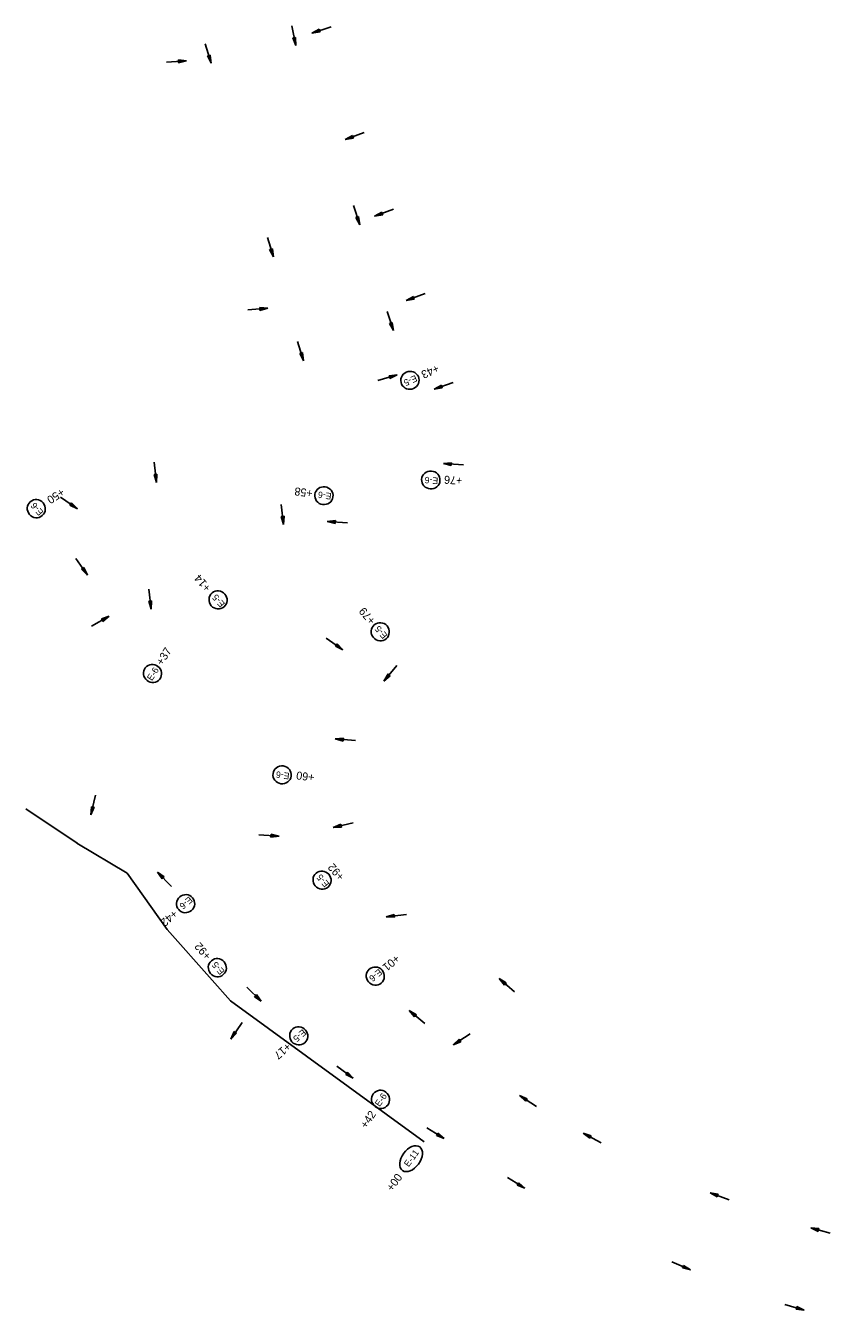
# Model space of a CAD drawing. Extents: x 918344 to 920005, y 1764082 to 1766125.
# Drawn here: x 919402 to 920005, y 1764082 to 1765046 of the extents above; entities that cross this region are included whole.
import ezdxf

# ---------------------------------------------------------------- set-up
doc = ezdxf.new("R2010")
doc.units = 0
for name, color, linetype in [('43', 7, 'Continuous'), ('44', 7, 'Continuous'), ('EC_CG', 7, 'Continuous'), ('Level 1', 7, 'Continuous')]:
    doc.layers.add(name, color=color, linetype=linetype)

msp = doc.modelspace()

# ---------------------------------------------------------------- linework, layer by layer
at = {"layer": '43'}
for p, q in [((919602.32, 1765036.58), (919604.42, 1765036.98)), ((919604.51, 1765030.81), (919602.32, 1765036.58)), ((919604.42, 1765036.98), (919604.51, 1765030.81)), ((919616.63, 1765040.13), (919622.07, 1765043.04)), ((919622.74, 1765041), (919616.63, 1765040.13)), ((919622.07, 1765043.04), (919622.74, 1765041)), ((919516.67, 1765017.94), (919516.5, 1765020.08)), ((919516.5, 1765020.08), (919522.64, 1765019.48)), ((919522.64, 1765019.48), (919516.67, 1765017.94)), ((919538.23, 1765023.02), (919540.28, 1765023.64)), ((919541.01, 1765017.51), (919538.23, 1765023.02)), ((919540.28, 1765023.64), (919541.01, 1765017.51)), ((919641.62, 1764960.43), (919646.97, 1764963.51)), ((919647.7, 1764961.49), (919641.62, 1764960.43)), ((919646.97, 1764963.51), (919647.7, 1764961.49)), ((919649.55, 1764901.92), (919651.6, 1764902.57)), ((919652.42, 1764896.46), (919649.55, 1764901.92)), ((919651.6, 1764902.57), (919652.42, 1764896.46)), ((919663.6, 1764902.91), (919668.95, 1764905.99)), ((919669.68, 1764903.97), (919663.6, 1764902.91)), ((919668.95, 1764905.99), (919669.68, 1764903.97)), ((919584.9, 1764877.8), (919586.96, 1764878.42)), ((919587.69, 1764872.29), (919584.9, 1764877.8)), ((919586.96, 1764878.42), (919587.69, 1764872.29)), ((919687.31, 1764839.63), (919692.66, 1764842.71)), ((919692.66, 1764842.71), (919693.39, 1764840.69)), ((919577.66, 1764832.26), (919577.49, 1764834.4)), ((919577.49, 1764834.4), (919583.63, 1764833.8)), ((919583.63, 1764833.8), (919577.66, 1764832.26)), ((919693.39, 1764840.69), (919687.31, 1764839.63)), ((919674.86, 1764822.52), (919676.9, 1764823.17)), ((919676.9, 1764823.17), (919677.72, 1764817.06)), ((919677.72, 1764817.06), (919674.86, 1764822.52)), ((919607.44, 1764800), (919609.48, 1764800.65)), ((919610.31, 1764794.54), (919607.44, 1764800)), ((919609.48, 1764800.65), (919610.31, 1764794.54)), ((919674.47, 1764783.2), (919680.6, 1764783.88)), ((919675.07, 1764781.14), (919674.47, 1764783.2)), ((919680.6, 1764783.88), (919675.07, 1764781.14)), ((919708.31, 1764773.08), (919713.65, 1764776.16)), ((919713.65, 1764776.16), (919714.39, 1764774.14)), ((919714.39, 1764774.14), (919708.31, 1764773.08)), ((919715.14, 1764717.38), (919721.27, 1764718.05)), ((919721.13, 1764715.9), (919715.14, 1764717.38)), ((919721.27, 1764718.05), (919721.13, 1764715.9)), ((919498.26, 1764709.17), (919500.39, 1764709.43)), ((919500.04, 1764703.27), (919498.26, 1764709.17)), ((919500.39, 1764709.43), (919500.04, 1764703.27)), ((919435.14, 1764686.11), (919436.35, 1764687.88)), ((919440.76, 1764683.57), (919435.14, 1764686.11)), ((919436.35, 1764687.88), (919440.76, 1764683.57)), ((919593.55, 1764677.61), (919595.68, 1764677.87)), ((919595.34, 1764671.71), (919593.55, 1764677.61)), ((919595.68, 1764677.87), (919595.34, 1764671.71)), ((919628.05, 1764674), (919634.18, 1764674.67)), ((919634.04, 1764672.53), (919628.05, 1764674)), ((919634.18, 1764674.67), (919634.04, 1764672.53)), ((919443.93, 1764638.16), (919445.69, 1764639.38)), ((919448.27, 1764633.78), (919443.93, 1764638.16)), ((919445.69, 1764639.38), (919448.27, 1764633.78)), ((919494.32, 1764614.14), (919496.45, 1764614.39)), ((919496.11, 1764608.23), (919494.32, 1764614.14)), ((919496.45, 1764614.39), (919496.11, 1764608.23)), ((919458.8, 1764600.9), (919464.64, 1764602.88)), ((919464.64, 1764602.88), (919459.83, 1764599.02)), ((919459.83, 1764599.02), (919458.8, 1764600.9)), ((919634.25, 1764580.38), (919635.46, 1764582.16)), ((919635.46, 1764582.16), (919639.87, 1764577.85)), ((919639.87, 1764577.85), (919634.25, 1764580.38)), ((919670.64, 1764554.32), (919673.72, 1764559.67)), ((919675.36, 1764558.29), (919670.64, 1764554.32)), ((919673.72, 1764559.67), (919675.36, 1764558.29)), ((919634.11, 1764510.92), (919640.25, 1764511.49)), ((919640.08, 1764509.35), (919634.11, 1764510.92)), ((919640.25, 1764511.49), (919640.08, 1764509.35)), ((919450.94, 1764453.97), (919451.3, 1764460.13)), ((919453.39, 1764459.64), (919450.94, 1764453.97)), ((919451.3, 1764460.13), (919453.39, 1764459.64)), ((919585.81, 1764437.34), (919585.95, 1764439.48)), ((919591.95, 1764438.02), (919585.81, 1764437.34)), ((919585.95, 1764439.48), (919591.95, 1764438.02)), ((919632.65, 1764444.49), (919638.31, 1764446.94)), ((919638.81, 1764444.85), (919632.65, 1764444.49)), ((919638.31, 1764446.94), (919638.81, 1764444.85)), ((919500.73, 1764411.08), (919505.76, 1764407.5)), ((919504.23, 1764405.99), (919500.73, 1764411.08)), ((919505.76, 1764407.5), (919504.23, 1764405.99)), ((919672.39, 1764377.65), (919678.32, 1764379.36)), ((919678.54, 1764377.23), (919672.39, 1764377.65)), ((919678.32, 1764379.36), (919678.54, 1764377.23)), ((919757.05, 1764331.21), (919762.32, 1764328.01)), ((919760.9, 1764326.39), (919757.05, 1764331.21)), ((919762.32, 1764328.01), (919760.9, 1764326.39)), ((919573.47, 1764317.67), (919574.97, 1764319.21)), ((919578.56, 1764314.19), (919573.47, 1764317.67)), ((919574.97, 1764319.21), (919578.56, 1764314.19)), ((919689.62, 1764307.2), (919694.99, 1764304.17)), ((919693.63, 1764302.51), (919689.62, 1764307.2)), ((919694.99, 1764304.17), (919693.63, 1764302.51)), ((919555.84, 1764285.88), (919558.39, 1764291.5)), ((919560.16, 1764290.28), (919555.84, 1764285.88)), ((919558.39, 1764291.5), (919560.16, 1764290.28)), ((919722.57, 1764281.52), (919727.11, 1764285.71)), ((919728.27, 1764283.91), (919722.57, 1764281.52)), ((919727.11, 1764285.71), (919728.27, 1764283.91)), ((919642.05, 1764259.34), (919643.33, 1764261.06)), ((919647.58, 1764256.6), (919642.05, 1764259.34)), ((919643.33, 1764261.06), (919647.58, 1764256.6)), ((919772.24, 1764243.49), (919777.95, 1764241.16)), ((919776.81, 1764239.34), (919772.24, 1764243.49)), ((919777.95, 1764241.16), (919776.81, 1764239.34)), ((919709.99, 1764213.6), (919711.13, 1764215.42)), ((919715.71, 1764211.29), (919709.99, 1764213.6)), ((919711.13, 1764215.42), (919715.71, 1764211.29)), ((919820.03, 1764215.35), (919825.89, 1764213.42)), ((919824.87, 1764211.53), (919820.03, 1764215.35)), ((919825.89, 1764213.42), (919824.87, 1764211.53)), ((919770.5, 1764176.34), (919771.64, 1764178.16)), ((919771.64, 1764178.16), (919776.22, 1764174.03)), ((919776.22, 1764174.03), (919770.5, 1764176.34)), ((919915.11, 1764170.61), (919921.18, 1764169.49)), ((919920.43, 1764167.48), (919915.11, 1764170.61)), ((919921.18, 1764169.49), (919920.43, 1764167.48)), ((919990.6, 1764144.29), (919996.75, 1764143.79)), ((919996.2, 1764141.71), (919990.6, 1764144.29)), ((919996.75, 1764143.79), (919996.2, 1764141.71)), ((919894.46, 1764114.23), (919895.3, 1764116.2)), ((919900.47, 1764112.84), (919894.46, 1764114.23)), ((919895.3, 1764116.2), (919900.47, 1764112.84)), ((919979.6, 1764083.24), (919980.23, 1764085.29)), ((919985.73, 1764082.5), (919979.6, 1764083.24)), ((919980.23, 1764085.29), (919985.73, 1764082.5))]:
    msp.add_line(p, q, dxfattribs=at)
for points in [[(919601.66, 1765045.73), (919604.51, 1765030.81)], [(919631.07, 1765044.85), (919616.63, 1765040.13)], [(919536.61, 1765032.05), (919541.01, 1765017.51)], [(919507.5, 1765018.3), (919522.64, 1765019.48)], [(919655.9, 1764965.6), (919641.62, 1764960.43)], [(919647.81, 1764910.93), (919652.42, 1764896.46)], [(919677.88, 1764908.08), (919663.6, 1764902.91)], [(919583.29, 1764886.83), (919587.69, 1764872.29)], [(919701.59, 1764844.8), (919687.31, 1764839.63)], [(919568.49, 1764832.63), (919583.63, 1764833.8)], [(919673.11, 1764831.53), (919677.72, 1764817.06)], [(919605.69, 1764809.01), (919610.31, 1764794.54)], [(919666.02, 1764779.61), (919680.6, 1764783.88)], [(919722.59, 1764778.25), (919708.31, 1764773.08)], [(919498.24, 1764718.35), (919500.04, 1764703.27)], [(919730.29, 1764716.37), (919715.14, 1764717.38)], [(919428.22, 1764692.13), (919440.76, 1764683.57)], [(919593.54, 1764686.79), (919595.34, 1764671.71)], [(919643.2, 1764672.99), (919628.05, 1764674)], [(919439.61, 1764646.25), (919448.27, 1764633.78)], [(919494.31, 1764623.31), (919496.11, 1764608.23)], [(919451.32, 1764595.58), (919464.64, 1764602.88)], [(919627.33, 1764586.41), (919639.87, 1764577.85)], [(919680.39, 1764565.96), (919670.64, 1764554.32)], [(919649.25, 1764509.66), (919634.11, 1764510.92)], [(919454.45, 1764468.75), (919450.94, 1764453.97)], [(919647.42, 1764448.02), (919632.65, 1764444.49)], [(919576.79, 1764439), (919591.95, 1764438.02)], [(919511.38, 1764400.25), (919500.73, 1764411.08)], [(919687.49, 1764379.25), (919672.39, 1764377.65)], [(919567.71, 1764324.81), (919578.56, 1764314.19)], [(919768.45, 1764321.18), (919757.05, 1764331.21)], [(919701.36, 1764297.56), (919689.62, 1764307.2)], [(919564.42, 1764298.41), (919555.84, 1764285.88)], [(919735.35, 1764289.73), (919722.57, 1764281.52)], [(919635.35, 1764265.61), (919647.58, 1764256.6)], [(919785.09, 1764235.39), (919772.24, 1764243.49)], [(919702.83, 1764219.34), (919715.71, 1764211.29)], [(919833.4, 1764208.16), (919820.03, 1764215.35)], [(919763.34, 1764182.07), (919776.22, 1764174.03)], [(919929.34, 1764165.29), (919915.11, 1764170.61)], [(920005.28, 1764140.43), (919990.6, 1764144.29)], [(919886.49, 1764118.78), (919900.47, 1764112.84)], [(919971.2, 1764086.92), (919985.73, 1764082.5)]]:
    msp.add_lwpolyline(points, dxfattribs=at)
at = {"layer": 'EC_CG'}
for p, q in [((919440.52, 1764432.82), (919402, 1764458.59)), ((919440.52, 1764432.82), (919402, 1764458.59)), ((919440.52, 1764432.82), (919402, 1764458.59)), ((919440.52, 1764432.82), (919402, 1764458.59)), ((919478, 1764410.35), (919440.43, 1764432.87)), ((919478, 1764410.35), (919440.43, 1764432.87)), ((919478, 1764410.35), (919440.43, 1764432.87)), ((919507.97, 1764368.07), (919478, 1764410.35)), ((919507.97, 1764368.07), (919478, 1764410.35)), ((919541.92, 1764329.98), (919507.97, 1764368.07)), ((919541.92, 1764329.98), (919507.97, 1764368.07)), ((919555.63, 1764314.6), (919541.92, 1764329.98)), ((919555.63, 1764314.6), (919541.92, 1764329.98)), ((919555.63, 1764314.6), (919700.88, 1764208.8)), ((919555.63, 1764314.6), (919700.88, 1764208.8))]:
    msp.add_line(p, q, dxfattribs=at)
for centre, major_axis, ratio in [((919521.92, 1764387.41), (5.22, 4.48), 0.97521), ((919521.92, 1764387.41), (5.22, 4.48), 0.97521), ((919606.73, 1764288.26), (4.48, -5.22), 0.97521), ((919668.05, 1764240.67), (4.48, -5.22), 0.97521), ((919668.05, 1764240.67), (4.48, -5.22), 0.97521), ((919690.97, 1764196.19), (6.44, 8.87), 0.622952), ((919690.97, 1764196.19), (6.44, 8.87), 0.622952)]:
    msp.add_ellipse(centre, major_axis=major_axis, ratio=ratio, dxfattribs=at)
at = {"layer": 'Level 1'}
for centre, major_axis in [((919690.13, 1764779.8), (6.27, 2.83)), ((919705.75, 1764705.09), (6.87, -0.45)), ((919625.59, 1764693.33), (6.81, -0.95)), ((919409.94, 1764683.58), (4.48, -5.22)), ((919546.24, 1764615.17), (4.48, -5.22)), ((919667.84, 1764591.3), (4.48, -5.22)), ((919497.11, 1764560.02), (4.48, -5.22)), ((919594.25, 1764483.99), (6.82, -0.91)), ((919624.19, 1764405.05), (4.48, -5.22)), ((919545.7, 1764339.41), (4.48, -5.22)), ((919664.12, 1764333.13), (4.48, -5.22))]:
    msp.add_ellipse(centre, major_axis=major_axis, ratio=0.97521, dxfattribs=at)

# ---------------------------------------------------------------- texts
at = {"layer": '44'}
for s, rotation, p in [('+43', 204.22844, (919710.35, 1764791.89)), ('+76', 176.15879, (919729.52, 1764707.42)), ('+58', 172.01522, (919617.5, 1764697.78)), ('+50', 213.15765, (919428.7, 1764699.26)), ('+14', 130.58924, (919541.31, 1764624.49)), ('+79', 130.58924, (919664.7, 1764599.88)), ('+37', 57.49949, (919504.4, 1764565.54)), ('+60', 172.3709, (919618.84, 1764484.85)), ('+92', 130.58924, (919641.43, 1764407.91)), ('+92', 130.58924, (919541.49, 1764348.56)), ('+01', 220.58924, (919679.33, 1764349.62))]:
    msp.add_text(s, height=6, rotation=rotation, dxfattribs=at).set_placement(p)
at = {"layer": 'EC_CG'}
for s, height, rotation, p in [('E-6', 4.876, 220.64727, (919524.49, 1764393.12)), ('+42', 6, 220.58924, (919512.77, 1764383.2)), ('+42', 6, 220.58924, (919512.77, 1764383.2)), ('E-5', 4.876, 220.64727, (919609.68, 1764293.6)), ('+17', 6, 220.58924, (919597.85, 1764283.59)), ('E-6', 4.876, 55.50218, (919667.39, 1764234.78)), ('E-6', 4.876, 55.50218, (919667.39, 1764234.78)), ('+42', 6, 55.44416, (919657.28, 1764218.31)), ('+42', 6, 55.44416, (919657.28, 1764218.31)), ('E-11 ', 4.876, 54.01706, (919689.15, 1764189.61)), ('E-11 ', 4.876, 54.01706, (919689.15, 1764189.61)), ('+00', 6, 54.02022, (919676.81, 1764171.19)), ('+00', 6, 54.02022, (919676.81, 1764171.19))]:
    msp.add_text(s, height=height, rotation=rotation, dxfattribs=at).set_placement(p)
at = {"layer": 'Level 1'}
for s, rotation, p in [('E-5', 204.28647, (919694.1, 1764783.92)), ('E-6', 176.21682, (919711.45, 1764706.84)), ('E-6', 172.07325, (919631.57, 1764695.17)), ('E-6', 130.64727, (919415.64, 1764681.01)), ('E-5', 130.64727, (919551.73, 1764612.24)), ('E-5', 130.64727, (919673.64, 1764588.63)), ('E-6', 57.55752, (919496.66, 1764554.09)), ('E-6', 172.42892, (919600.05, 1764485.36)), ('E-5', 130.64727, (919629.99, 1764402.37)), ('E-5', 130.64727, (919551.5, 1764336.73)), ('E-6', 220.64727, (919666.69, 1764338.83))]:
    msp.add_text(s, height=4.876, rotation=rotation, dxfattribs=at).set_placement(p)

doc.saveas('drawing.dxf')
